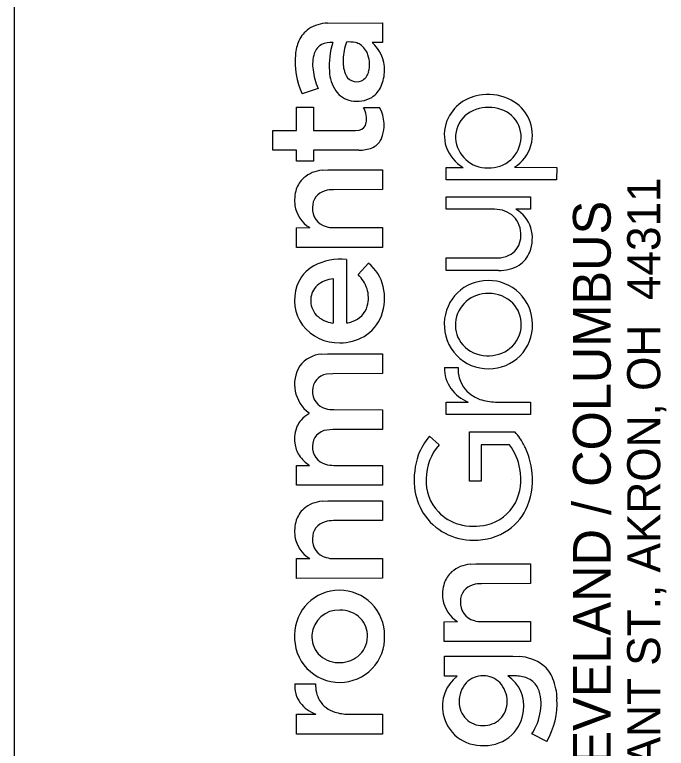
# Model space of a CAD drawing. Extents: x 0 to 1700, y 0 to 1100.
# Drawn here: x 1600 to 1649.2, y 154.7 to 210.1 of the extents above; entities that cross this region are included whole.
import ezdxf

# ---------------------------------------------------------------- set-up
doc = ezdxf.new("R2010")
doc.units = 0
doc.layers.add('SH_Border', color=7, linetype='Continuous')
doc.layers.add('SH_Data', color=7, linetype='Continuous')

msp = doc.modelspace()

# ---------------------------------------------------------------- linework, layer by layer
at = {"layer": 'SH_Border'}
msp.add_line((1600, 25), (1600, 1075), dxfattribs=at)
at = {"layer": 'SH_Data'}
for p, q in [((1623.633, 209.45), (1627.776, 209.459)), ((1627.776, 209.459), (1627.786, 207.978)), ((1627.786, 207.978), (1626.986, 207.978)), ((1622.909, 204.522), (1621.715, 204.116)), ((1621.271, 201.352), (1621.274, 203.104)), ((1621.274, 203.104), (1622.554, 203.104)), ((1622.554, 203.104), (1622.559, 201.352)), ((1626.348, 203.08), (1627.555, 203.08)), ((1619.482, 201.35), (1621.271, 201.352)), ((1619.482, 199.86), (1619.482, 201.35)), ((1622.559, 201.352), (1625.749, 201.352)), ((1625.749, 201.352), (1626.002, 201.375)), ((1621.271, 199.859), (1619.482, 199.86)), ((1621.271, 199.033), (1621.271, 199.859)), ((1625.984, 199.859), (1622.554, 199.858)), ((1622.554, 199.858), (1622.554, 199.033)), ((1622.554, 199.033), (1621.271, 199.033)), ((1623.219, 198.343), (1623.645, 198.366)), ((1623.645, 198.366), (1627.785, 198.366)), ((1627.785, 198.366), (1627.786, 196.877)), ((1632.576, 197.607), (1632.576, 198.557)), ((1632.576, 198.557), (1633.855, 198.557)), ((1637.746, 198.566), (1640.929, 198.554)), ((1640.929, 198.554), (1640.921, 197.607)), ((1640.921, 197.607), (1632.576, 197.607)), ((1627.786, 196.877), (1624.07, 196.873)), ((1632.576, 195.4), (1632.576, 196.336)), ((1632.576, 196.336), (1638.955, 196.332)), ((1638.955, 196.332), (1638.954, 195.398)), ((1636.245, 195.398), (1632.576, 195.4)), ((1636.64, 195.364), (1636.245, 195.398)), ((1638.954, 195.398), (1637.845, 195.398)), ((1621.271, 194.008), (1622.276, 194.01)), ((1621.271, 192.517), (1621.271, 194.008)), ((1624.111, 194.01), (1627.785, 194.01)), ((1627.785, 194.01), (1627.786, 192.522)), ((1627.786, 192.522), (1621.271, 192.517)), ((1625.054, 191.604), (1625.059, 186.829)), ((1632.577, 191.722), (1636.453, 191.725)), ((1632.583, 190.771), (1632.577, 191.722)), ((1625.941, 190.463), (1626.711, 191.331)), ((1636.537, 190.771), (1632.583, 190.771)), ((1624.072, 186.822), (1624.072, 190.148)), ((1624.008, 186.814), (1624.072, 186.822)), ((1623.165, 184.457), (1623.629, 184.484)), ((1623.629, 184.484), (1627.779, 184.484)), ((1627.779, 184.484), (1627.786, 182.991)), ((1632.466, 183.453), (1633.489, 183.453)), ((1624.029, 182.99), (1623.551, 182.941)), ((1627.786, 182.991), (1624.029, 182.99)), ((1632.576, 179.9), (1632.576, 180.85)), ((1632.576, 180.85), (1634.238, 180.85)), ((1636.302, 180.851), (1638.955, 180.848)), ((1638.955, 180.848), (1638.952, 179.9)), ((1622.222, 179.961), (1622.228, 180.036)), ((1624.109, 180.276), (1627.786, 180.274)), ((1627.786, 180.274), (1627.786, 178.784)), ((1638.952, 179.9), (1632.576, 179.9)), ((1624.045, 178.783), (1623.572, 178.737)), ((1627.786, 178.784), (1624.045, 178.783)), ((1634.34, 178.592), (1637.758, 178.596)), ((1634.34, 174.889), (1634.34, 178.592)), ((1631.318, 178.274), (1632.057, 177.621)), ((1635.224, 177.62), (1635.216, 174.888)), ((1637.368, 177.614), (1635.224, 177.62)), ((1621.271, 174.576), (1621.272, 176.069)), ((1621.272, 176.069), (1622.257, 176.069)), ((1624.103, 176.069), (1627.786, 176.068)), ((1627.786, 176.068), (1627.786, 174.578)), ((1637.5, 175), (1637.5, 175)), ((1627.786, 174.578), (1621.271, 174.576)), ((1635.216, 174.888), (1634.34, 174.889)), ((1623.219, 173.368), (1623.645, 173.391)), ((1623.645, 173.391), (1627.785, 173.391)), ((1627.785, 173.391), (1627.786, 171.902)), ((1627.786, 171.902), (1624.07, 171.898)), ((1621.271, 169.033), (1622.276, 169.036)), ((1621.271, 167.543), (1621.271, 169.033)), ((1624.111, 169.036), (1627.785, 169.036)), ((1627.785, 169.036), (1627.786, 167.548)), ((1634.392, 168.61), (1634.817, 168.633)), ((1634.817, 168.633), (1638.958, 168.633)), ((1638.958, 168.633), (1638.958, 167.144)), ((1627.786, 167.548), (1621.271, 167.543)), ((1638.958, 167.144), (1635.242, 167.14)), ((1632.444, 164.275), (1633.449, 164.277)), ((1632.444, 162.785), (1632.444, 164.275)), ((1635.284, 164.277), (1638.957, 164.277)), ((1638.957, 164.277), (1638.958, 162.789)), ((1638.958, 162.789), (1632.444, 162.785)), ((1632.445, 160.168), (1632.445, 161.661)), ((1632.445, 161.661), (1637.618, 161.661)), ((1637.618, 161.661), (1638.096, 161.643)), ((1633.418, 160.168), (1632.445, 160.168)), ((1637.881, 160.178), (1637.243, 160.181)), ((1621.149, 159.597), (1622.727, 159.597)), ((1621.271, 155.797), (1621.271, 157.289)), ((1621.271, 157.289), (1622.736, 157.289)), ((1625.206, 157.29), (1627.786, 157.287)), ((1627.786, 157.287), (1627.782, 155.797)), ((1627.782, 155.797), (1621.271, 155.797)), ((1640.18, 155.245), (1639.06, 155.799))]:
    msp.add_line(p, q, dxfattribs=at)
for points in [[(1623.633, 209.45), (1627.776, 209.459), (1627.786, 207.978)], [(1627.786, 207.978), (1626.986, 207.978)], [(1622.909, 204.522), (1621.715, 204.116)], [(1625.984, 199.859), (1622.554, 199.858), (1622.554, 199.033), (1621.271, 199.033), (1621.271, 199.859), (1619.482, 199.86), (1619.482, 201.35), (1621.271, 201.352), (1621.274, 203.104), (1622.554, 203.104), (1622.559, 201.352), (1625.749, 201.352), (1626.002, 201.375)], [(1626.348, 203.08), (1627.555, 203.08)], [(1623.219, 198.343), (1623.645, 198.366), (1627.785, 198.366), (1627.786, 196.877), (1624.07, 196.873)], [(1637.746, 198.566), (1640.929, 198.554), (1640.921, 197.607), (1632.576, 197.607)], [(1632.576, 197.607), (1632.576, 198.557), (1633.855, 198.557)], [(1636.64, 195.364), (1636.245, 195.398), (1632.576, 195.4), (1632.576, 196.336), (1638.955, 196.332), (1638.954, 195.398), (1637.845, 195.398)], [(1621.271, 192.517), (1621.271, 194.008), (1622.276, 194.01)], [(1624.111, 194.01), (1627.785, 194.01), (1627.786, 192.522), (1621.271, 192.517)], [(1625.054, 191.604), (1625.059, 186.829)], [(1636.537, 190.771), (1632.583, 190.771), (1632.577, 191.722), (1636.453, 191.725)], [(1625.941, 190.463), (1626.711, 191.331)], [(1624.008, 186.814), (1624.072, 186.822), (1624.072, 190.148)], [(1623.165, 184.457), (1623.629, 184.484), (1627.779, 184.484), (1627.786, 182.991), (1624.029, 182.99), (1623.551, 182.941)], [(1632.466, 183.453), (1633.489, 183.453)], [(1636.302, 180.851), (1638.955, 180.848), (1638.952, 179.9), (1632.576, 179.9)], [(1632.576, 179.9), (1632.576, 180.85), (1634.238, 180.85)], [(1622.222, 179.961), (1622.228, 180.036)], [(1624.109, 180.276), (1627.786, 180.274), (1627.786, 178.784), (1624.045, 178.783), (1623.572, 178.737)], [(1637.368, 177.614), (1635.224, 177.62), (1635.216, 174.888), (1634.34, 174.889), (1634.34, 178.592), (1637.758, 178.596)], [(1631.318, 178.274), (1632.057, 177.621)], [(1621.271, 174.576), (1621.272, 176.069), (1622.257, 176.069)], [(1624.103, 176.069), (1627.786, 176.068), (1627.786, 174.578), (1621.271, 174.576)], [(1623.219, 173.368), (1623.645, 173.391), (1627.785, 173.391), (1627.786, 171.902), (1624.07, 171.898)], [(1621.271, 167.543), (1621.271, 169.033), (1622.276, 169.036)], [(1624.111, 169.036), (1627.785, 169.036), (1627.786, 167.548), (1621.271, 167.543)], [(1634.392, 168.61), (1634.817, 168.633), (1638.958, 168.633), (1638.958, 167.144), (1635.242, 167.14)], [(1632.444, 162.785), (1632.444, 164.275), (1633.449, 164.277)], [(1635.284, 164.277), (1638.957, 164.277), (1638.958, 162.789), (1632.444, 162.785)], [(1633.418, 160.168), (1632.445, 160.168), (1632.445, 161.661), (1637.618, 161.661), (1638.096, 161.643)], [(1637.881, 160.178), (1637.243, 160.181)], [(1621.149, 159.597), (1622.727, 159.597)], [(1625.206, 157.29), (1627.786, 157.287), (1627.782, 155.797), (1621.271, 155.797)], [(1621.271, 155.797), (1621.271, 157.289), (1622.736, 157.289)], [(1640.18, 155.245), (1639.06, 155.799)]]:
    msp.add_lwpolyline(points, dxfattribs=at)
for centre, radius, start, end in [((1623.726, 206.628), 2.823, 91.8942, 122.6317), ((1623.726, 206.628), 2.823, 91.8942, 122.6317), ((1623.423, 207.234), 2.151, 124.537, 155.6594), ((1623.423, 207.234), 2.151, 124.537, 155.6594), ((1624.412, 206.806), 3.228, 155.9764, 175.3149), ((1624.412, 206.806), 3.228, 155.9764, 175.3149), ((1623.763, 206.78), 1.2, 119.4252, 161.6629), ((1623.763, 206.78), 1.2, 119.4252, 161.6629), ((1623.893, 206.389), 1.607, 85.3802, 116.6222), ((1623.893, 206.389), 1.607, 85.3802, 116.6222), ((1629.394, 206.254), 5.645, 162.0821, 184.5285), ((1629.394, 206.254), 5.645, 162.0821, 184.5285), ((1629.007, 206.566), 4.205, 159.8366, 178.0362), ((1629.007, 206.566), 4.205, 159.8366, 178.0362), ((1625.255, 205.371), 2.651, 79.6696, 94.2322), ((1625.255, 205.371), 2.651, 79.6696, 94.2322), ((1625.446, 206.822), 1.192, 56.8913, 76.2149), ((1625.446, 206.822), 1.192, 56.8913, 76.2149), ((1625.26, 206.592), 1.486, 17.5984, 55.7282), ((1625.26, 206.592), 1.486, 17.5984, 55.7282), ((1625.276, 205.957), 2.647, 358.0746, 49.762), ((1625.276, 205.957), 2.647, 358.0746, 49.762), ((1626.82, 206.539), 5.65, 174.6101, 205.3899), ((1626.82, 206.539), 5.65, 174.6101, 205.3899), ((1625.379, 206.323), 2.879, 163.1369, 188.1675), ((1625.379, 206.323), 2.879, 163.1369, 188.1675), ((1627.328, 206.515), 2.531, 175.5903, 199.8857), ((1627.328, 206.515), 2.531, 175.5903, 199.8857), ((1624.58, 206.32), 2.217, 345.9408, 18.9919), ((1624.58, 206.32), 2.217, 345.9408, 18.9919), ((1627.363, 206.487), 4.867, 186.7598, 203.7981), ((1627.363, 206.487), 4.867, 186.7598, 203.7981), ((1626.639, 205.937), 2.876, 182.5676, 213.7144), ((1626.639, 205.937), 2.876, 182.5676, 213.7144), ((1625.821, 205.943), 0.92, 198.2844, 293.3081), ((1625.821, 205.943), 0.92, 198.2844, 293.3081), ((1625.76, 205.997), 0.995, 295.2883, 347.4639), ((1625.76, 205.997), 0.995, 295.2883, 347.4639), ((1625.093, 205.839), 2.828, 336.016, 0.5951), ((1625.093, 205.839), 2.828, 336.016, 0.5951), ((1625.743, 205.391), 1.828, 215.0668, 259.8133), ((1625.743, 205.391), 1.828, 215.0668, 259.8133), ((1625.876, 205.485), 1.969, 303.4436, 336.18), ((1625.876, 205.485), 1.969, 303.4436, 336.18), ((1625.877, 205.655), 2.113, 257.5256, 300.882), ((1625.877, 205.655), 2.113, 257.5256, 300.882), ((1635.54, 200.912), 3.122, 93.9866, 158.3119), ((1635.54, 200.912), 3.122, 93.9866, 158.3119), ((1635.779, 200.325), 3.729, 62.6889, 97.0135), ((1635.779, 200.325), 3.729, 62.6889, 97.0135), ((1636.062, 200.957), 3.038, 25.0657, 61.9602), ((1636.062, 200.957), 3.038, 25.0657, 61.9602), ((1624.313, 202.099), 2.259, 10.1545, 25.723), ((1624.313, 202.099), 2.259, 10.1545, 25.723), ((1625.151, 201.753), 2.746, 336.589, 28.8991), ((1625.151, 201.753), 2.746, 336.589, 28.8991), ((1635.69, 200.508), 2.567, 87.8965, 131.1812), ((1635.69, 200.508), 2.567, 87.8965, 131.1812), ((1635.875, 200.511), 2.564, 49.9089, 92.0363), ((1635.875, 200.511), 2.564, 49.9089, 92.0363), ((1624.786, 202.182), 1.778, 351.914, 10.2059), ((1624.786, 202.182), 1.778, 351.914, 10.2059), ((1635.46, 200.837), 2.169, 132.3289, 182.0949), ((1635.46, 200.837), 2.169, 132.3289, 182.0949), ((1636.077, 200.866), 2.163, 358.0487, 47.9447), ((1636.077, 200.866), 2.163, 358.0487, 47.9447), ((1636.225, 201.002), 2.871, 301.9776, 25.6418), ((1636.225, 201.002), 2.871, 301.9776, 25.6418), ((1625.919, 202.001), 0.632, 277.6142, 353.7918), ((1625.919, 202.001), 0.632, 277.6142, 353.7918), ((1635.348, 201.008), 2.907, 158.656, 198.171), ((1635.348, 201.008), 2.907, 158.656, 198.171), ((1626.456, 201.306), 1.375, 292.6889, 332.0598), ((1626.456, 201.306), 1.375, 292.6889, 332.0598), ((1635.676, 200.907), 2.388, 183.5974, 271.7045), ((1635.676, 200.907), 2.388, 183.5974, 271.7045), ((1635.859, 200.901), 2.383, 267.3149, 357.4019), ((1635.859, 200.901), 2.383, 267.3149, 357.4019), ((1626.044, 202.428), 2.569, 268.6727, 291.5235), ((1626.044, 202.428), 2.569, 268.6727, 291.5235), ((1635.515, 201.217), 3.135, 200.8399, 238.0162), ((1635.515, 201.217), 3.135, 200.8399, 238.0162), ((1623.435, 195.858), 2.494, 94.9706, 130.2248), ((1623.435, 195.858), 2.494, 94.9706, 130.2248), ((1623.174, 196.275), 2.008, 132.2238, 161.6823), ((1623.174, 196.275), 2.008, 132.2238, 161.6823), ((1623.936, 196.054), 2.801, 162.274, 187.7917), ((1623.936, 196.054), 2.801, 162.274, 187.7917), ((1623.741, 195.578), 1.249, 103.6868, 182.214), ((1623.741, 195.578), 1.249, 103.6868, 182.214), ((1624.054, 194.573), 2.3, 89.6051, 105.3303), ((1624.054, 194.573), 2.3, 89.6051, 105.3303), ((1623.513, 196.045), 2.381, 188.9646, 238.6987), ((1623.513, 196.045), 2.381, 188.9646, 238.6987), ((1623.868, 195.423), 1.378, 175.5844, 255.1382), ((1623.868, 195.423), 1.378, 175.5844, 255.1382), ((1636.355, 193.499), 1.886, 33.5008, 81.3295), ((1636.355, 193.499), 1.886, 33.5008, 81.3295), ((1636.62, 193.242), 2.48, 17.6221, 60.3897), ((1636.62, 193.242), 2.48, 17.6221, 60.3897), ((1636.207, 193.475), 2.024, 346.5618, 31.7539), ((1636.207, 193.475), 2.024, 346.5618, 31.7539), ((1624.092, 196.118), 2.107, 254.0891, 270.5284), ((1624.092, 196.118), 2.107, 254.0891, 270.5284), ((1636.172, 193.207), 2.919, 339.162, 15.6148), ((1636.172, 193.207), 2.919, 339.162, 15.6148), ((1636.685, 193.308), 1.521, 294.6321, 348.4863), ((1636.685, 193.308), 1.521, 294.6321, 348.4863), ((1636.95, 192.951), 2.101, 303.1039, 338.1561), ((1636.95, 192.951), 2.101, 303.1039, 338.1561), ((1624.588, 187.437), 4.193, 83.6212, 118.2845), ((1624.588, 187.437), 4.193, 83.6212, 118.2845), ((1636.374, 194.041), 2.317, 271.952, 294.0894), ((1636.374, 194.041), 2.317, 271.952, 294.0894), ((1623.947, 188.684), 2.791, 118.8294, 160.6224), ((1623.947, 188.684), 2.791, 118.8294, 160.6224), ((1624.7, 188.815), 3.221, 13.5328, 51.3627), ((1624.7, 188.815), 3.221, 13.5328, 51.3627), ((1636.605, 193.628), 2.857, 268.627, 301.4778), ((1636.605, 193.628), 2.857, 268.627, 301.4778), ((1624.017, 188.509), 2.743, 19.0387, 45.4432), ((1624.017, 188.509), 2.743, 19.0387, 45.4432), ((1624.22, 188.035), 2.118, 94.0131, 130.8806), ((1624.22, 188.035), 2.118, 94.0131, 130.8806), ((1635.717, 186.742), 3.276, 89.4821, 178.7775), ((1635.717, 186.742), 3.276, 89.4821, 178.7775), ((1635.791, 186.707), 3.312, 0.4227, 90.7613), ((1635.791, 186.707), 3.312, 0.4227, 90.7613), ((1624.348, 188.537), 3.219, 160.5214, 215.7815), ((1624.348, 188.537), 3.219, 160.5214, 215.7815), ((1623.851, 188.545), 1.492, 132.9855, 177.1802), ((1623.851, 188.545), 1.492, 132.9855, 177.1802), ((1624.362, 188.716), 2.35, 344.6072, 17.0067), ((1624.362, 188.716), 2.35, 344.6072, 17.0067), ((1624.145, 188.692), 3.79, 339.3543, 13.3771), ((1624.145, 188.692), 3.79, 339.3543, 13.3771), ((1635.698, 186.622), 2.423, 87.6883, 175.017), ((1635.698, 186.622), 2.423, 87.6883, 175.017), ((1635.83, 186.518), 2.526, 44.912, 90.7591), ((1635.83, 186.518), 2.526, 44.912, 90.7591), ((1623.912, 188.483), 1.557, 175.0014, 223.2876), ((1623.912, 188.483), 1.557, 175.0014, 223.2876), ((1635.978, 186.726), 2.274, 358.3228, 43.8349), ((1635.978, 186.726), 2.274, 358.3228, 43.8349), ((1624.948, 188.589), 1.752, 288.0108, 343.5536), ((1624.948, 188.589), 1.752, 288.0108, 343.5536), ((1624.273, 188.913), 2.116, 225.0645, 262.797), ((1624.273, 188.913), 2.116, 225.0645, 262.797), ((1624.774, 188.491), 3.13, 300.9439, 338.7322), ((1624.774, 188.491), 3.13, 300.9439, 338.7322), ((1624.454, 188.758), 3.436, 217.7434, 271.6561), ((1624.454, 188.758), 3.436, 217.7434, 271.6561), ((1625.064, 187.839), 1.01, 269.7004, 294.8729), ((1625.064, 187.839), 1.01, 269.7004, 294.8729), ((1635.742, 186.67), 3.303, 177.5373, 270.9452), ((1635.742, 186.67), 3.303, 177.5373, 270.9452), ((1635.542, 186.656), 2.265, 175.5147, 221.4205), ((1635.542, 186.656), 2.265, 175.5147, 221.4205), ((1635.836, 186.636), 3.268, 269.3083, 1.6791), ((1635.836, 186.636), 3.268, 269.3083, 1.6791), ((1635.966, 186.687), 2.286, 308.9038, 359.3095), ((1635.966, 186.687), 2.286, 308.9038, 359.3095), ((1624.602, 188.851), 3.528, 269.2053, 300.3357), ((1624.602, 188.851), 3.528, 269.2053, 300.3357), ((1635.699, 186.867), 2.523, 222.6626, 268.3733), ((1635.699, 186.867), 2.523, 222.6626, 268.3733), ((1623.319, 182.202), 2.261, 93.9112, 142.3072), ((1623.319, 182.202), 2.261, 93.9112, 142.3072), ((1635.783, 186.929), 2.589, 266.5531, 308.6725), ((1635.783, 186.929), 2.589, 266.5531, 308.6725), ((1623.793, 182.186), 2.66, 148.2879, 233.9556), ((1623.793, 182.186), 2.66, 148.2879, 233.9556), ((1634.939, 183.331), 2.476, 177.1621, 216.2802), ((1634.939, 183.331), 2.476, 177.1621, 216.2802), ((1635.867, 183.319), 2.382, 176.7699, 252.1504), ((1635.867, 183.319), 2.382, 176.7699, 252.1504), ((1623.692, 181.75), 1.2, 96.7576, 181.6251), ((1623.692, 181.75), 1.2, 96.7576, 181.6251), ((1623.788, 181.621), 1.299, 175.8157, 256.1672), ((1623.788, 181.621), 1.299, 175.8157, 256.1672), ((1635.488, 183.777), 3.183, 216.9153, 246.8862), ((1635.488, 183.777), 3.183, 216.9153, 246.8862), ((1636.345, 184.587), 3.736, 251.1388, 269.3469), ((1636.345, 184.587), 3.736, 251.1388, 269.3469), ((1623.19, 178.133), 2.068, 117.9163, 139.243), ((1623.19, 178.133), 2.068, 117.9163, 139.243), ((1624.085, 182.527), 2.25, 254.3463, 270.6103), ((1624.085, 182.527), 2.25, 254.3463, 270.6103), ((1623.097, 178.226), 1.937, 139.5245, 154.847), ((1623.097, 178.226), 1.937, 139.5245, 154.847), ((1623.572, 178.06), 2.439, 156.0638, 187.3493), ((1623.572, 178.06), 2.439, 156.0638, 187.3493), ((1623.711, 177.528), 1.217, 96.5532, 179.949), ((1623.711, 177.528), 1.217, 96.5532, 179.949), ((1636.249, 176.969), 2.219, 30.9891, 47.161), ((1636.249, 176.969), 2.219, 30.9891, 47.161), ((1623.23, 177.987), 2.091, 186.5579, 213.3885), ((1623.23, 177.987), 2.091, 186.5579, 213.3885), ((1635.081, 175.093), 4.928, 139.7948, 159.137), ((1635.081, 175.093), 4.928, 139.7948, 159.137), ((1633.546, 175.009), 5.553, 25.3031, 33.9618), ((1633.546, 175.009), 5.553, 25.3031, 33.9618), ((1623.804, 177.431), 1.314, 175.722, 255.7863), ((1623.804, 177.431), 1.314, 175.722, 255.7863), ((1634.95, 175.04), 3.877, 138.258, 179.7006), ((1634.95, 175.04), 3.877, 138.258, 179.7006), ((1633.944, 175.049), 4.278, 10.0751, 36.8319), ((1633.944, 175.049), 4.278, 10.0751, 36.8319), ((1633.52, 174.993), 5.583, 8.8034, 25.3348), ((1633.52, 174.993), 5.583, 8.8034, 25.3348), ((1623.943, 178.539), 2.99, 214.7043, 235.6872), ((1623.943, 178.539), 2.99, 214.7043, 235.6872), ((1635.935, 174.984), 5.768, 161.1438, 185.6281), ((1635.935, 174.984), 5.768, 161.1438, 185.6281), ((1624.097, 178.259), 2.19, 253.6672, 270.1498), ((1624.097, 178.259), 2.19, 253.6672, 270.1498), ((1634.212, 175.028), 4.018, 333.4669, 11.0367), ((1634.212, 175.028), 4.018, 333.4669, 11.0367), ((1633.782, 174.989), 5.325, 338.2887, 9.2855), ((1633.782, 174.989), 5.325, 338.2887, 9.2855), ((1634.406, 174.866), 3.338, 176.6658, 223.6912), ((1634.406, 174.866), 3.338, 176.6658, 223.6912), ((1634.668, 174.85), 4.493, 185.5077, 212.0129), ((1634.668, 174.85), 4.493, 185.5077, 212.0129), ((1623.435, 170.884), 2.494, 94.9706, 130.2248), ((1623.435, 170.884), 2.494, 94.9706, 130.2248), ((1623.174, 171.301), 2.008, 132.2238, 161.6823), ((1623.174, 171.301), 2.008, 132.2238, 161.6823), ((1634.934, 174.773), 3.26, 282.8815, 331.8147), ((1634.934, 174.773), 3.26, 282.8815, 331.8147), ((1634.918, 174.584), 4.12, 305.0306, 337.6757), ((1634.918, 174.584), 4.12, 305.0306, 337.6757), ((1634.606, 174.874), 4.454, 212.7022, 270.714), ((1634.606, 174.874), 4.454, 212.7022, 270.714), ((1634.523, 175.006), 3.519, 224.0215, 253.88), ((1634.523, 175.006), 3.519, 224.0215, 253.88), ((1623.936, 171.079), 2.801, 162.274, 187.7917), ((1623.936, 171.079), 2.801, 162.274, 187.7917), ((1623.741, 170.603), 1.249, 103.6868, 182.214), ((1623.741, 170.603), 1.249, 103.6868, 182.214), ((1624.054, 169.598), 2.3, 89.6051, 105.3303), ((1624.054, 169.598), 2.3, 89.6051, 105.3303), ((1634.659, 175.627), 4.154, 254.4535, 283.9512), ((1634.659, 175.627), 4.154, 254.4535, 283.9512), ((1634.715, 174.989), 4.569, 269.3273, 304.1963), ((1634.715, 174.989), 4.569, 269.3273, 304.1963), ((1623.513, 171.071), 2.381, 188.9646, 238.6987), ((1623.513, 171.071), 2.381, 188.9646, 238.6987), ((1623.868, 170.449), 1.378, 175.5844, 255.1382), ((1623.868, 170.449), 1.378, 175.5844, 255.1382), ((1624.092, 171.143), 2.107, 254.0891, 270.5284), ((1624.092, 171.143), 2.107, 254.0891, 270.5284), ((1634.608, 166.125), 2.494, 94.9706, 130.2248), ((1634.608, 166.125), 2.494, 94.9706, 130.2248), ((1634.347, 166.543), 2.008, 132.2238, 161.6823), ((1634.347, 166.543), 2.008, 132.2238, 161.6823), ((1635.109, 166.321), 2.801, 162.274, 187.7917), ((1635.109, 166.321), 2.801, 162.274, 187.7917), ((1634.914, 165.845), 1.249, 103.6868, 182.214), ((1634.914, 165.845), 1.249, 103.6868, 182.214), ((1635.227, 164.84), 2.3, 89.6051, 105.3303), ((1635.227, 164.84), 2.3, 89.6051, 105.3303), ((1624.507, 163.271), 3.37, 89.8476, 179.6405), ((1624.507, 163.271), 3.37, 89.8476, 179.6405), ((1624.529, 163.237), 3.405, 359.5401, 90.2114), ((1624.529, 163.237), 3.405, 359.5401, 90.2114), ((1634.686, 166.312), 2.381, 188.9646, 238.6987), ((1634.686, 166.312), 2.381, 188.9646, 238.6987), ((1635.04, 165.69), 1.378, 175.5844, 255.1382), ((1635.04, 165.69), 1.378, 175.5844, 255.1382), ((1624.461, 163.132), 2.02, 87.0481, 175.5726), ((1624.461, 163.132), 2.02, 87.0481, 175.5726), ((1624.602, 163), 2.149, 45.8426, 90.9801), ((1624.602, 163), 2.149, 45.8426, 90.9801), ((1624.729, 163.211), 1.911, 357.8857, 44.159), ((1624.729, 163.211), 1.911, 357.8857, 44.159), ((1635.264, 166.385), 2.107, 254.0891, 270.5284), ((1635.264, 166.385), 2.107, 254.0891, 270.5284), ((1624.541, 163.104), 3.409, 176.8344, 270.4038), ((1624.541, 163.104), 3.409, 176.8344, 270.4038), ((1624.365, 163.125), 1.924, 175.1538, 221.1471), ((1624.365, 163.125), 1.924, 175.1538, 221.1471), ((1624.562, 163.069), 3.374, 270.0624, 2.3776), ((1624.562, 163.069), 3.374, 270.0624, 2.3776), ((1624.723, 163.159), 1.915, 308.2894, 359.4347), ((1624.723, 163.159), 1.915, 308.2894, 359.4347), ((1624.459, 163.303), 2.114, 223.0999, 268.8089), ((1624.459, 163.303), 2.114, 223.0999, 268.8089), ((1624.548, 163.395), 2.209, 266.5651, 308.0608), ((1624.548, 163.395), 2.209, 266.5651, 308.0608), ((1637.953, 158.394), 3.251, 53.4034, 87.4906), ((1637.953, 158.394), 3.251, 53.4034, 87.4906), ((1638.259, 159.02), 2.571, 21.6075, 50.5577), ((1638.259, 159.02), 2.571, 21.6075, 50.5577), ((1635.146, 157.906), 2.846, 127.3748, 192.2247), ((1635.146, 157.906), 2.846, 127.3748, 192.2247), ((1635.347, 158.464), 1.73, 88.473, 136.4256), ((1635.347, 158.464), 1.73, 88.473, 136.4256), ((1635.407, 158.481), 1.712, 44.2719, 90.4762), ((1635.407, 158.481), 1.712, 44.2719, 90.4762), ((1635.71, 157.914), 2.736, 352.1125, 55.923), ((1635.71, 157.914), 2.736, 352.1125, 55.923), ((1637.833, 157.862), 2.316, 65.0169, 88.8011), ((1637.833, 157.862), 2.316, 65.0169, 88.8011), ((1623.308, 159.441), 2.164, 175.8731, 216.3475), ((1623.308, 159.441), 2.164, 175.8731, 216.3475), ((1625.043, 159.474), 2.32, 176.9688, 209.6064), ((1625.043, 159.474), 2.32, 176.9688, 209.6064), ((1635.571, 158.301), 2.005, 137.4674, 182.3324), ((1635.571, 158.301), 2.005, 137.4674, 182.3324), ((1635.184, 158.3), 1.998, 358.5714, 43.5376), ((1635.184, 158.3), 1.998, 358.5714, 43.5376), ((1638.13, 158.578), 1.543, 26.2681, 63.803), ((1638.13, 158.578), 1.543, 26.2681, 63.803), ((1636.535, 158.357), 4.418, 1.1514, 21.3627), ((1636.535, 158.357), 4.418, 1.1514, 21.3627), ((1636.783, 158.077), 2.976, 349.3073, 23.4307), ((1636.783, 158.077), 2.976, 349.3073, 23.4307), ((1635.269, 158.122), 5.692, 329.6388, 3.26), ((1635.269, 158.122), 5.692, 329.6388, 3.26), ((1623.733, 159.858), 2.755, 218.0981, 248.7907), ((1623.733, 159.858), 2.755, 218.0981, 248.7907), ((1624.757, 159.407), 2.039, 211.9447, 253.2028), ((1624.757, 159.407), 2.039, 211.9447, 253.2028), ((1635.323, 158.185), 1.755, 178.8821, 271.0837), ((1635.323, 158.185), 1.755, 178.8821, 271.0837), ((1635.409, 158.202), 1.773, 268.2788, 1.5502), ((1635.409, 158.202), 1.773, 268.2788, 1.5502), ((1625.233, 160.825), 3.535, 252.4655, 269.573), ((1625.233, 160.825), 3.535, 252.4655, 269.573), ((1635.232, 157.848), 2.919, 190.7518, 231.2892), ((1635.232, 157.848), 2.919, 190.7518, 231.2892), ((1635.494, 157.854), 2.944, 313.742, 353.8554), ((1635.494, 157.854), 2.944, 313.742, 353.8554), ((1635.369, 158.167), 4.385, 327.3149, 351.5748), ((1635.369, 158.167), 4.385, 327.3149, 351.5748), ((1635.477, 157.951), 3.026, 269.6361, 312.7088), ((1635.477, 157.951), 3.026, 269.6361, 312.7088), ((1635.316, 158.056), 3.134, 232.4606, 272.5902), ((1635.316, 158.056), 3.134, 232.4606, 272.5902)]:
    msp.add_arc(centre, radius, start, end, dxfattribs=at)

# ---------------------------------------------------------------- texts
for s, height, p in [('450 GRANT ST., AKRON, OH  44311', 2.49231, (1648.744, 141.869)), ('AKRON / CLEVELAND / COLUMBUS', 2.84845, (1645.006, 131.9))]:
    msp.add_text(s, height=height, rotation=90, dxfattribs=at).set_placement(p)

doc.saveas('drawing.dxf')
